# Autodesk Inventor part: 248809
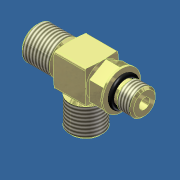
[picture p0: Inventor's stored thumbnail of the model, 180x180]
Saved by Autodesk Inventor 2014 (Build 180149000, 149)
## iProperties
Shininess: 20.0
Length Units: 11272
Angle Units: 11279
Time Units: 11290
Mass Units: 11286
Length Display Precision: 3
Angle Display Precision: 2
Company: Autodesk, Inc.
Created: 2002-06
Part Number: 248809
Material: Stainless Steel, 440C
Description: Fitting; TE-C9C9G20-(SS)
Document SubType Name: Modeling
Designer: Autodesk, Inc.
Density: 7.75 g/cm^3
Mass: 1443.65 g
Surface Area: 415.754 cm^2
Volume: 186.278 cm^3
Appearance: Stainless Steel
Density: 0.0
Volumn: 0.0
Area: 0.0
PropertySet Name: Model Information
Control State: 0
Master: False
Checked Out: True
Last Check In By: JT
Last Check In Date: 2003-06-20
Title: Fitting; TE-C9C9G20-(SS)
Author: Autodesk, Inc.
Comments: -
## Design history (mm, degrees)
derived "C9C9G-C9GC9.ipt"
body "Solid1"
tag "TaggingFeature2"
feature "Solid1::C9C9G-C9GC9.ipt" dims "ScaleForDerivedMember" = 10
